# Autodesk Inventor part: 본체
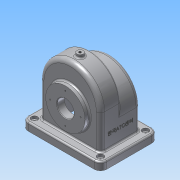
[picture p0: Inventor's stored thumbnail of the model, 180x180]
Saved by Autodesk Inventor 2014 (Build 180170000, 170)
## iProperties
Created: 2017-11
Part Number: 본체
Material: 알루미늄 6061
Document SubType Name: Modeling
Designer: sda
Density: 2.71 g/cm^3
Appearance: 알루미늄 - 평지
Mass: 1079.49 g
Surface Area: 1182.07 cm^2
Volume: 398.334 cm^3
Author: sda
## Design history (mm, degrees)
sketch "스케치1"
  geometry: L1 (38, -58)-(-38, -58); L2 (-38, -58)-(-38, 58); L3 (-38, 58)-(38, 58); L4 (38, 58)-(38, -58); L5 (38, -58)-(-38, 58); L6 (-38, -58)-(38, 58); 1 further point
  constraints: 12 end point, 2 midpoint, 2 parallel, 1 horizontal, 1 perpendicular
  dimensions: "d0" = 76 distance of L2.end L3.end; "d1" = 116 distance of L1.end L2.end
extrude "돌출1" new body sketch "스케치1" distance "d2" = 80; taper "d3" = 0 deg
sketch "스케치3"
  geometry: L1 (38, 58)-(-38, 58) reference; L2 (-38, 58)-(-38, -58) reference; L3 (38, -58)-(38, 58) reference; L4 (-38, 0)-(38, 0); L5 (38, 58)-(38, -58) reference; L6 (38, -58)-(-38, -58) reference; L7 (-38, -58)-(-38, 58) reference; L8 (-38, 58)-(38, 58) reference; L9 (-38, 0)-(-38, 58); L10 (38, 58)-(38, 0); L11 (38, 58)-(-38, 58); 1 further point
  constraints: 8 end point, 2 collinear, 2 midpoint, 1 perpendicular
revolve "회전1" sketch "스케치3" stored, may be unused: angle "d4" = 180 deg
sketch "스케치4"
  geometry: L1 (116, 0)-(0, 0) reference; L2 (116, 0)-(116, 80) reference; L3 (0, 0)-(0, 80) reference; L4 (0, 57)-(116, 57); A1 r 58 centre (58, 80) between (116, 80) and (0, 80) reference; A2 r 58 centre (58, 57) between (116, 57) and (0, 57); 1 further point
  constraints: 2 end point, 2 point on circle, 2 point on line, 1 centre point, 1 perpendicular
  dimensions: "d5" = 57 distance between parallel lines of L1 L4; "d6" = 58 radius of A2
extrude "돌출2" cut sketch "스케치4" distance "d7" = 38; taper "d8" = 0 deg
feature "쉘1" dims "d9" = 5
node "작업 평면1"
sketch "스케치5"
  geometry: L1 (-43, 75)-(43, 75); L2 (55, 63)-(55, -63); L3 (43, -75)-(-43, -75); L4 (-55, -63)-(-55, 63); L5 (-55, 75)-(55, -75); L6 (55, 75)-(-55, -75); L7 (33, 53)-(-33, 53) reference; L8 (-33, 53)-(-33, -53) reference; L9 (-33, -53)-(33, -53) reference; L10 (33, -53)-(33, 53) reference; L11 (-38, 58)-(38, 58) reference; L12 (38, 58)-(38, -58) reference; L13 (38, -58)-(-38, -58) reference; L14 (-38, -58)-(-38, 58) reference; A1 r 12 centre (-43, 63) between (-43, 75) and (-55, 63); A2 r 12 centre (43, 63) between (55, 63) and (43, 75); A3 r 12 centre (43, -63) between (43, -75) and (55, -63); A4 r 12 centre (-43, -63) between (-55, -63) and (-43, -75); 1 further point
  constraints: 12 end point, 8 point on circle, 8 point on line, 8 tangent, 4 centre point, 3 equal radius, 2 midpoint, 2 parallel, 1 horizontal, 1 perpendicular
  dimensions: "d11" = 110 distance of L5.end L6.end; "d12" = 150 distance of L6.start L5.end; "d13" = 12 radius of A1
extrude "돌출3" join sketch "스케치5" distance "d14" = 15; taper "d15" = 0 deg
sketch "스케치6"
  geometry: L1 (-63, -80)-(63, -80) reference; C1 r 37.5 at (0, -15); 2 further points
  constraints: 1 centre point, 1 midpoint, 1 vertical alignment
  dimensions: "d16" = 75 diameter of C1; "d17" = 65 distance from line of L1 C1.centre
extrude "돌출4" join sketch "스케치6" distance "d18" = 9; taper "d19" = 0 deg
sketch "스케치7"
  geometry: L1 (-63, -57)-(63, -57) reference; C1 r 31 at (0, 8); 2 further points
  constraints: 1 centre point, 1 midpoint, 1 vertical alignment
  dimensions: "d20" = 62 diameter of C1; "d21" = 65 distance from line of L1 C1.centre
extrude "돌출5" join sketch "스케치7" distance "d22" = 10; taper "d23" = 0 deg
sketch "스케치8"
  geometry: C1 r 37.5 at (0, 0) reference; C2 r 16 at (0, 0); 1 further point
  constraints: 1 centre point, 1 coincident
  dimensions: "d24" = 32 diameter of C2
extrude "돌출6" cut sketch "스케치8" stored distance "d25" = 10; taper "d26" = 0 deg
sketch "스케치9"
  geometry: C1 r 16 at (0, 0) reference; 2 further points
  constraints: 1 vertical alignment
  dimensions: "d27" = 29 distance of C1.centre point (0, 29)
hole "구멍1" sketch "스케치9" at (0, 29) diameter "d28" = 2.459; stored, may be unused: countersink angle "d32" = 90 deg, drill point angle "d34" = 118 deg; dims "d29" = 6, "d30" = 4, "d31" = 2, "d33" = 8
sketch "스케치10"
  geometry: C1 r 16 at (0, 0) reference; 2 further points
  constraints: 1 vertical alignment
  dimensions: "d38" = 26 distance of C1.centre point (0, 26)
hole "구멍2" sketch "스케치10" at (0, 26) diameter "d39" = 2.459; stored, may be unused: countersink angle "d43" = 90 deg, drill point angle "d45" = 118 deg; dims "d40" = 6, "d41" = 4, "d42" = 2, "d44" = 8
node "작업 평면2"
sketch "스케치11"
  geometry: L1 (38, 58)-(38, -58) reference; L2 (-43, -75)-(43, -75) reference; C1 r 6 at (19, 0); 1 further point
  constraints: 1 centre point
  dimensions: "d50" = 19 distance from line of L1 C1.centre; "d51" = 75 distance from line of L2 C1.centre; "d52" = 12 diameter of C1
extrude "돌출7" join sketch "스케치11" stored distance "d53" = 10; taper "d54" = 0 deg
hole "구멍3" diameter "d57" = 4.459; stored, may be unused: countersink angle "d61" = 90 deg, drill point angle "d63" = 118 deg; dims "d58" = 6, "d59" = 4, "d60" = 2, "d62" = 8, "d86" = 10, "d87" = 10
sketch "스케치12"
  geometry: A1 r 12 centre (43, -63) between (43, -75) and (55, -63) reference; A2 r 12 centre (43, 63) between (55, 63) and (43, 75) reference; A3 r 12 centre (-43, 63) between (-43, 75) and (-55, 63) reference; A4 r 12 centre (-43, -63) between (-55, -63) and (-43, -75) reference; 5 further points
  constraints: 4 coincident
hole "구멍4" sketch "스케치12" at (-43, 63), (43, 63), (43, -63), (-43, -63) diameter "d64" = 5; stored, may be unused: countersink angle "d68" = 90 deg, drill point angle "d70" = 118 deg; dims "d65" = 6, "d66" = 12, "d67" = 5, "d69" = 8
fillet "모깎기1" dims "d71" = 8
fillet "모깎기3" dims "d73" = 3
fillet "모깎기4" dims "d74" = 3
fillet "모깎기5" dims "d75" = 3
fillet "모깎기6" dims "d76" = 3
fillet "모깎기7" dims "d77" = 3
chamfer "모따기1" distance "d78" = 1; stored, may be unused: second distance "d79" = 2, angle "d80" = 45 deg
node "작업 평면3"
sketch "스케치13"
  geometry: L1 (-35, 23)-(-35, -39) reference; L2 (-40, -57)-(46, -57) reference; 2 further points
  constraints: 1 other
  dimensions: "d82" = 38 distance from line of L1 point (3, -17); "d83" = 40 distance of point (3, -57) point (3, -17)
feature "엠보싱1" sketch "스케치13" dims "d0" = 76, "d1" = 116, "d84" = 0.5, "d85" = 0
node "솔리드1"
pattern_circular "원형 패턴1" dims angle "d36" = 360 deg
pattern_circular "원형 패턴2" dims angle "d47" = 360 deg
node "절단 모서리 투영1"
node "절단 모서리 투영2"
other parameters: "d10" = 0, "d49" = 144, "d81" = 11.25
